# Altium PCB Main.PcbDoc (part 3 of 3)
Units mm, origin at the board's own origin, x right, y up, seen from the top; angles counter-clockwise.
Board outline 160.02 x 109 mm, 4 copper layers (Top Layer, MidLayer1, MidLayer2, Bottom Layer), stack 1.588 mm thick; 321 components, 271 nets, 1178 pads, 515 vias.
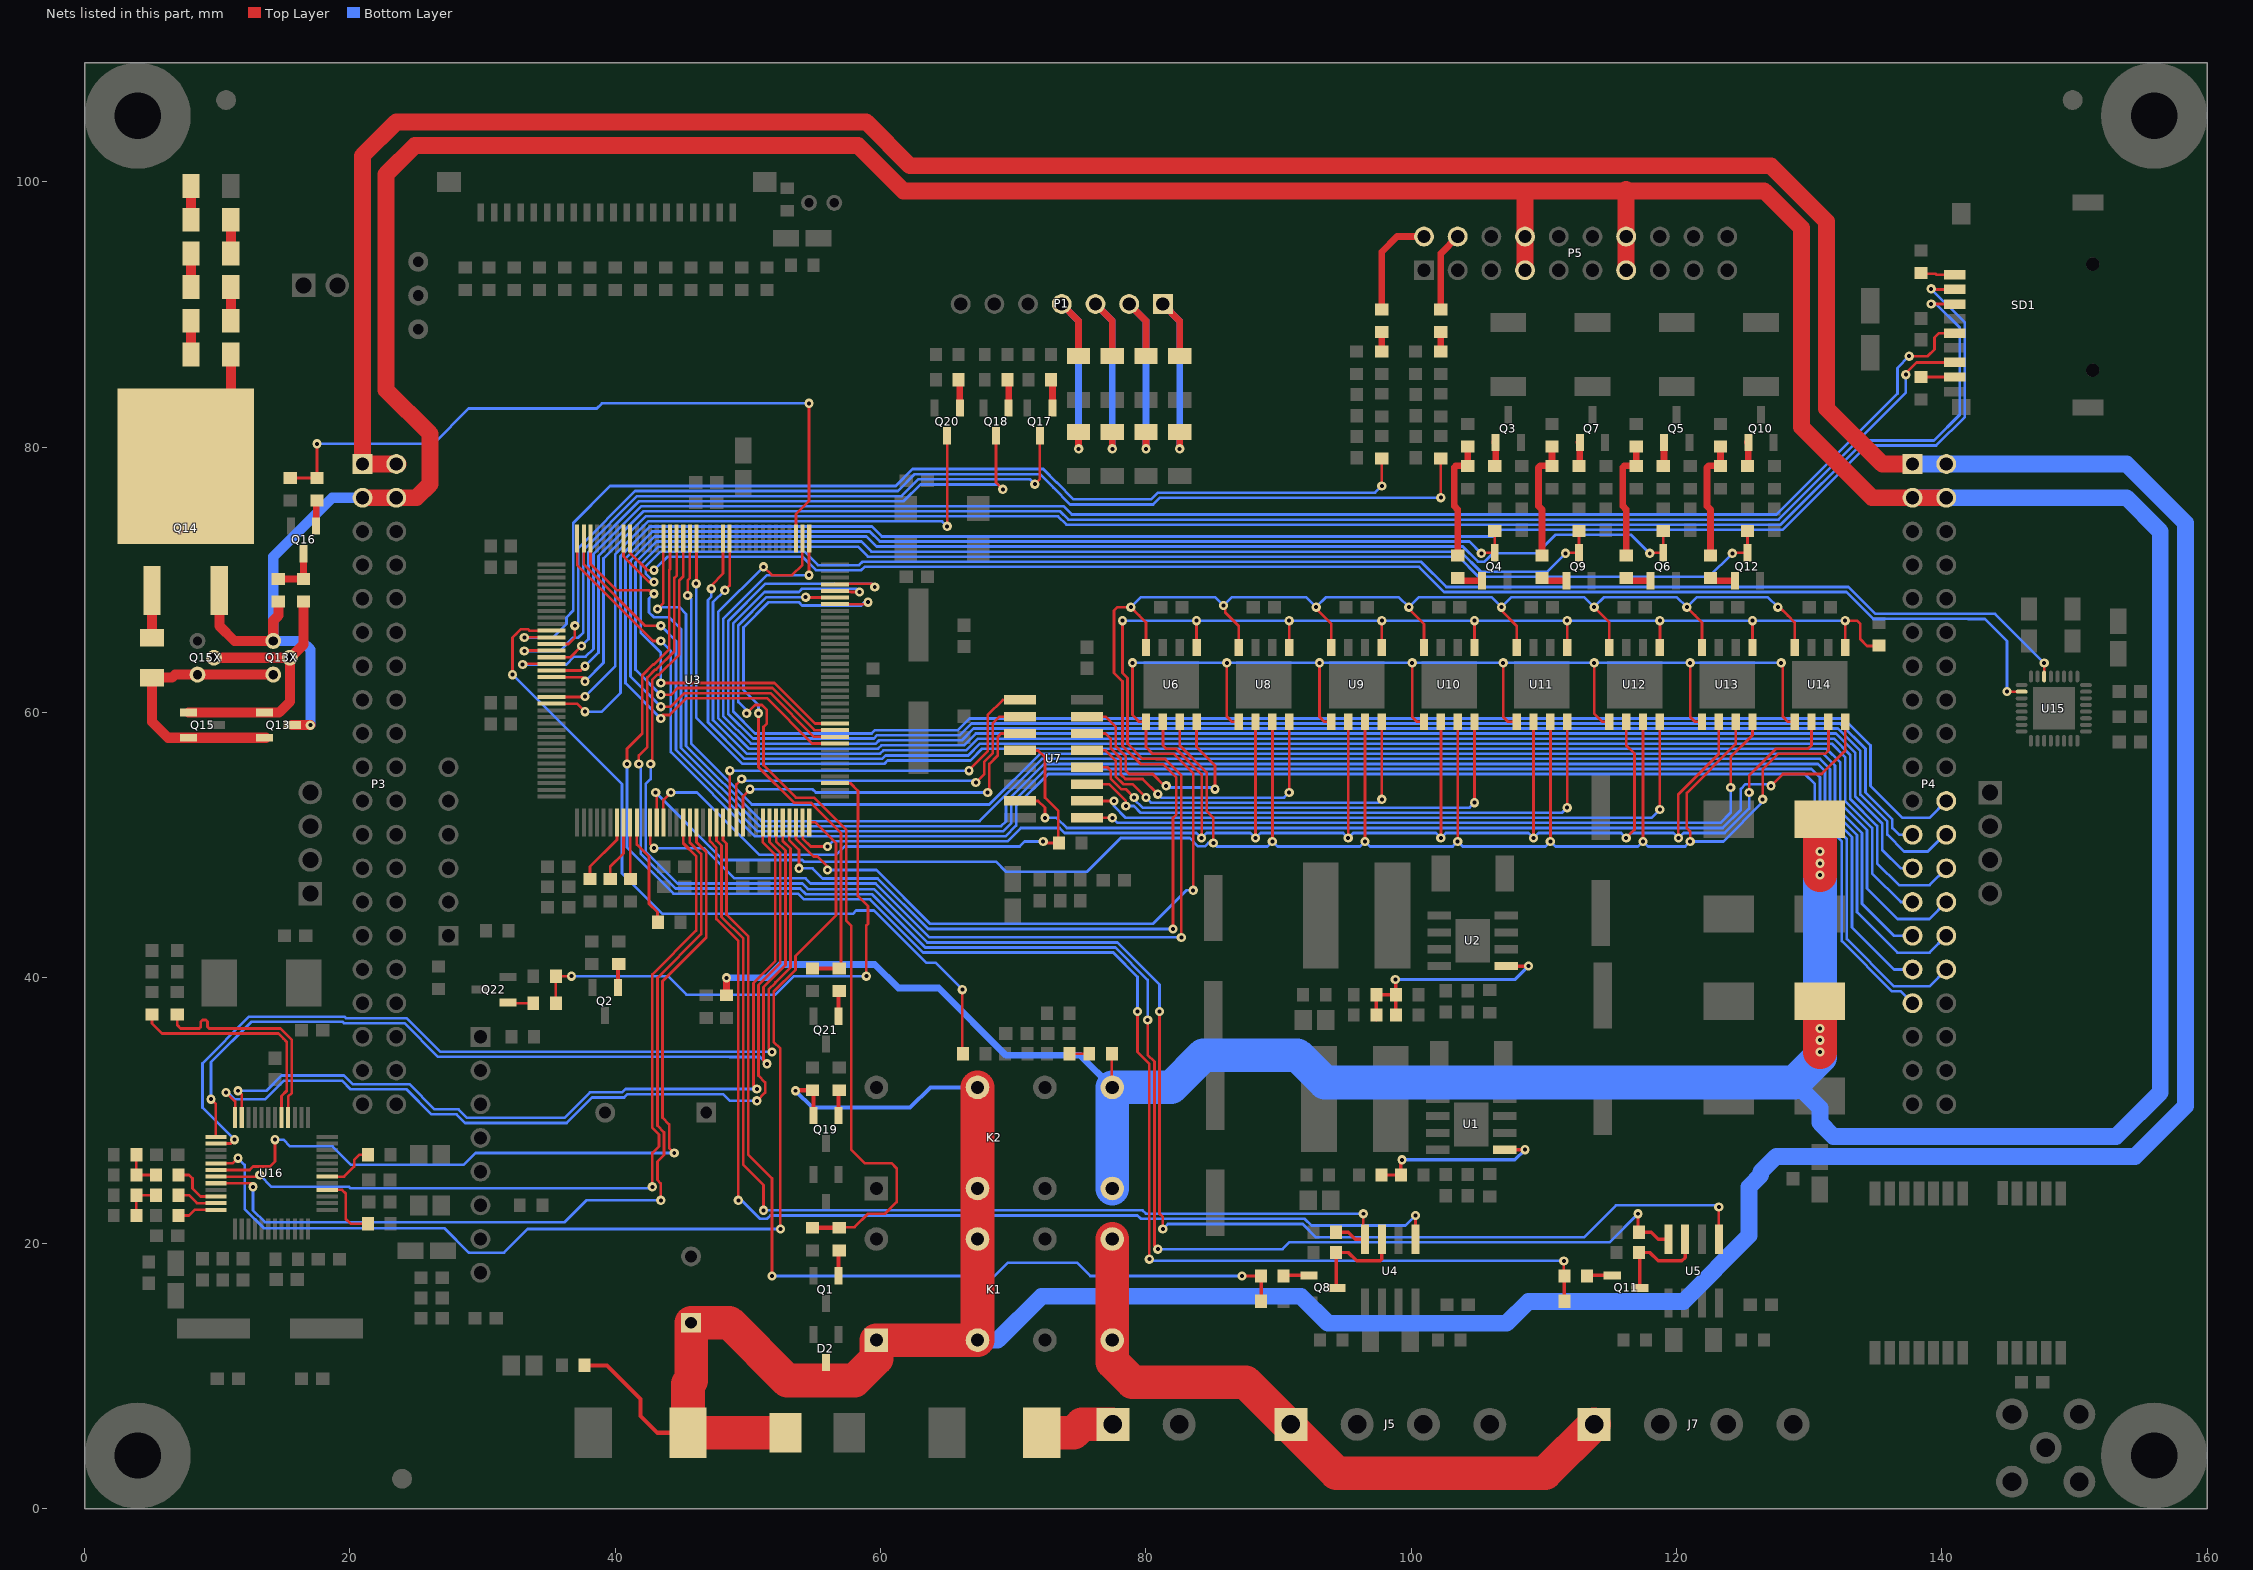
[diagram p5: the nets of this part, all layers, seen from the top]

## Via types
v1: diameter 0.7, hole 0.3, Top Layer to Bottom Layer, tented both sides, 515 vias

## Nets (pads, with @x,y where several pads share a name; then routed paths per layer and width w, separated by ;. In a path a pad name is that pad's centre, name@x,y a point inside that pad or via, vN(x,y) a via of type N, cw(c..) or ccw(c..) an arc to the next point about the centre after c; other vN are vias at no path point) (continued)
NetP4_22: P4.22 U3.104 | length 117.3
  Top Layer w0.203: U3.104@56.579,69.174 56.647,69.106 57.749,69.106 57.767,69.088 v1(58.42,69.088)
  Bottom Layer w0.203: v1(58.42,69.088) 58.172,69.336 54.095,69.336 53.847,69.088 51.245,69.088 48.901,66.743 48.901,60.064 50.539,58.426 59.334,58.426 59.588,58.68 65.824,58.68 66.707,59.563 132.588,59.563 134.62,57.531 134.62,54.483 137.033,52.07 139.065,52.07 P4.22@140.335,53.34
NetP4_23: P4.23 U3.105 | length 118.7
  Top Layer w0.203: U3.105@56.579,69.674 56.622,69.717 59.315,69.717 v1(59.563,69.469)
  Bottom Layer w0.203: v1(59.563,69.469) 59.309,69.723 51.341,69.723 48.52,66.901 48.52,59.906 50.381,58.045 59.492,58.045 59.746,58.299 65.981,58.299 66.865,59.182 132.334,59.182 134.239,57.277 134.239,53.975 136.271,51.943 136.271,51.308 136.779,50.8 P4.23@137.795,50.8
NetP4_24: P4.24 U3.109 | length 118.5
  Top Layer w0.203: v1(54.61,70.358) U3.109@54.61,73.279
  Bottom Layer w0.203: v1(54.61,70.358) 51.438,70.358 48.139,67.059 48.139,59.749 50.224,57.664 59.65,57.664 59.904,57.918 66.139,57.918 67.023,58.801 132.176,58.801 133.858,57.119 133.858,53.817 135.89,51.785 135.89,50.8 137.16,49.53 138.938,49.53 P4.24@140.335,50.927
NetP4_25: P4.25 U3.110 | length 117
  Top Layer w0.203: v1(51.181,70.993) 51.816,70.358 53.34,70.358 54.102,71.12 U3.110@54.102,73.025
  Bottom Layer w0.203: v1(51.181,70.993) 47.758,67.57 47.758,59.591 50.066,57.283 59.808,57.283 60.062,57.537 66.297,57.537 67.18,58.42 132.018,58.42 133.477,56.961 133.477,53.659 135.509,51.627 135.509,49.657 136.906,48.26 P4.25@137.795,48.26
NetP4_26: P4.26 U3.121 | length 117.4
  Top Layer w0.203: v1(48.26,69.215) 48.628,69.583 U3.121@48.628,73.126
  Bottom Layer w0.203: v1(48.26,69.215) 47.377,68.332 47.377,59.433 49.908,56.902 59.965,56.902 60.219,57.156 66.455,57.156 67.338,58.039 131.861,58.039 133.096,56.804 133.096,53.502 135.128,51.47 135.128,48.641 136.779,46.99 139.065,46.99 P4.26@140.335,48.26
NetP4_27: P4.27 U3.122 | length 115.6
  Top Layer w0.203: v1(47.244,69.342) 47.244,69.596 48.128,70.48 U3.122@48.128,73.126
  Bottom Layer w0.203: v1(47.244,69.342) 47.244,68.738 46.996,68.489 46.996,59.275 49.75,56.521 60.123,56.521 60.377,56.775 66.613,56.775 67.496,57.658 131.703,57.658 132.715,56.646 132.715,53.344 134.747,51.312 134.747,47.879 136.906,45.72 P4.27@137.795,45.72
NetP4_28: P4.28 U3.126 | length 119.9
  Top Layer w0.203: v1(46.101,69.723) 46.129,69.751 U3.126@46.129,73.126
  Bottom Layer w0.203: v1(46.101,69.723) 46.101,59.631 49.592,56.14 60.281,56.14 60.535,56.394 66.77,56.394 67.654,57.277 131.318,57.277 132.334,56.261 132.334,53.186 134.366,51.154 134.366,46.736 136.652,44.45 139.065,44.45 P4.28@140.335,45.72
NetP4_29: P4.29 U3.127 | length 121.8
  Top Layer w0.203: v1(45.466,68.834) 45.472,68.84 45.472,69.984 45.629,70.141 U3.127@45.629,73.126
  Bottom Layer w0.203: v1(45.466,68.834) 45.72,68.58 45.72,57.657 50.296,53.08 68.195,53.08 72.01,56.896 131.064,56.896 131.953,56.007 131.953,52.959 133.985,50.927 133.985,45.593 136.398,43.18 P4.29@137.795,43.18
NetP4_30: P4.30 U3.131 | length 128.9
  Top Layer w0.203: v1(43.18,67.818) 43.63,68.268 U3.131@43.63,73.126
  Bottom Layer w0.203: v1(43.18,67.818) 43.307,67.945 44.831,67.945 45.339,67.437 45.339,57.499 51.016,51.822 67.475,51.822 72.168,56.515 130.81,56.515 131.572,55.753 131.572,52.801 133.604,50.769 133.604,44.958 136.652,41.91 139.065,41.91 P4.30@140.335,43.18
NetP4_31: P4.31 U3.142 | length 131.3
  Top Layer w0.203: U3.142@38.131,73.126 38.131,71.216 40.132,69.215 42.545,69.215 42.799,68.961 v1(42.926,68.961)
  Bottom Layer w0.203: v1(42.926,68.961) 42.551,68.586 42.551,67.557 42.919,67.189 44.063,67.189 44.958,66.294 44.958,57.341 50.859,51.441 69.095,51.441 69.463,51.809 69.463,53.272 72.326,56.134 130.652,56.134 131.191,55.595 131.191,52.643 133.223,50.611 133.223,43.815 136.398,40.64 P4.31@137.795,40.64
NetP4_32: P4.32 U3.143 | length 133.9
  Top Layer w0.203: U3.143@37.631,73.126 37.631,71.177 42.26,66.548 v1(43.434,66.548)
  Bottom Layer w0.203: v1(43.434,66.548) 44.577,65.405 44.577,57.183 50.701,51.06 69.253,51.06 69.844,51.651 69.844,53.114 72.484,55.753 130.175,55.753 130.81,55.118 130.81,52.486 132.842,50.454 132.842,42.926 136.398,39.37 139.065,39.37 P4.32@140.335,40.64
NetP4_33: P4.33 U3.144 | length 131.3
  Top Layer w0.203: U3.144@37.131,73.126 37.131,71.138 42.864,65.405 v1(43.434,65.405)
  Bottom Layer w0.203: v1(43.434,65.405) 44.196,64.643 44.196,57.026 50.543,50.679 69.41,50.679 70.225,51.494 70.225,52.956 72.641,55.372 129.667,55.372 130.429,54.61 130.429,52.328 132.461,50.296 132.461,42.768 136.24,38.989 136.906,38.989 P4.33@137.795,38.1
NetP5_2: P5.2 R28.1 | length 8
  Top Layer w0.508: R28.1@97.79,90.385 97.79,94.742 98.933,95.885 P5.2@100.965,95.885
NetP5_4: P5.4 R36.1 | length 6
  Top Layer w0.508: R36.1@102.235,90.385 102.235,94.615 P5.4@103.505,95.885
NetQ1_1: Q1.1 R6.2 | length 1.8
  Top Layer w0.305: Q1.1@56.83,17.56 R6.2@56.83,19.365
NetQ2_1: Q2.1 R17.2 | length 1.7
  Top Layer w0.305: Q2.1@40.193,39.277 R17.2@40.193,40.955
NetQ3_1: Q3.1 R25.1 | length 1.6
  Top Layer w0.508: Q3.1@106.299,80.357 Q3.1@106.299,80.391 ; R25.1@106.365,78.801 Q3.1@106.365,80.357
NetQ4_1: Q4.1 R33.2 | length 1.9
  Top Layer w0.508: R33.2@103.505,70.104 103.666,69.943 Q4.1@105.349,69.943
NetQ4_3: Q4.3 R26.2 U3.81 | length 97.2
  Top Layer w0.203: v1(43.434,59.563) 43.434,59.69 43.567,59.823 44.105,59.823 45.37,61.087 51.435,61.087 54.845,57.677 U3.81@56.579,57.677 ; v1(105.283,72.009) 105.317,72.043 Q4.3@106.299,72.043 R26.2@106.299,73.699
  Bottom Layer w0.203: v1(43.434,59.563) 40.773,62.223 40.773,71.631 42.796,73.654 59.188,73.654 59.944,72.898 104.394,72.898 v1(105.283,72.009)
NetQ5_1: Q5.1 R41.1 | length 1.6
  Top Layer w0.508: Q5.1@118.999,80.357 Q5.1@118.999,80.391 ; R41.1@119.065,78.801 Q5.1@119.065,80.357
NetQ6_1: Q6.1 R45.2 | length 1.9
  Top Layer w0.508: R45.2@116.205,70.104 116.366,69.943 Q6.1@118.049,69.943
NetQ6_3: Q6.3 R42.2 U3.82 | length 109.4
  Top Layer w0.203: v1(43.434,60.452) 44.196,60.452 45.212,61.468 51.689,61.468 54.98,58.177 U3.82@56.579,58.177 ; v1(117.983,72.009) 118.017,72.043 Q6.3@118.999,72.043 R42.2@118.999,73.699
  Bottom Layer w0.203: v1(43.434,60.452) 41.154,62.731 41.154,71.473 42.954,73.273 58.934,73.273 59.69,72.517 103.885,72.517 105.022,71.38 105.544,71.38 106.179,72.015 109.48,72.015 110.871,73.406 116.586,73.406 v1(117.983,72.009)
NetQ7_1: Q7.1 R51.1 | length 1.6
  Top Layer w0.508: Q7.1@112.649,80.357 Q7.1@112.649,80.391 ; R51.1@112.715,78.801 Q7.1@112.715,80.357
NetQ8_1: Q8.1 R53.2 | length 1.7
  Top Layer w0.254: R53.2@90.612,17.587 Q8.1@92.295,17.587
NetQ8_3: Q8.3 R48.2 U4.3 | length 8
  Top Layer w0.254: Q8.3@94.361,16.51 94.361,19.304 95.25,19.304 95.885,18.669 97.663,18.669 97.79,18.796 U4.3@97.79,20.307
NetQ9_1: Q9.1 R58.2 | length 1.9
  Top Layer w0.508: R58.2@109.855,70.104 110.016,69.943 Q9.1@111.699,69.943
NetQ9_3: Q9.3 R52.2 U3.83 | length 100.4
  Top Layer w0.203: v1(43.434,61.341) 44.196,61.341 44.704,61.849 51.847,61.849 55.019,58.677 U3.83@56.579,58.677 ; v1(111.633,72.009) 111.667,72.043 Q9.3@112.649,72.043 R52.2@112.649,73.699
  Bottom Layer w0.203: v1(43.434,61.341) 41.535,63.239 41.535,71.315 43.112,72.892 58.553,72.892 59.309,72.136 103.727,72.136 105.245,70.618 107.817,70.618 107.823,70.612 110.236,70.612 v1(111.633,72.009)
NetQ10_1: Q10.1 R63.1 | length 1.6
  Top Layer w0.508: Q10.1@125.349,80.357 Q10.1@125.349,80.391 ; R63.1@125.415,78.801 Q10.1@125.415,80.357
NetQ11_1: Q11.1 R67.2 | length 1.9
  Top Layer w0.254: R67.2@113.223,17.587 Q11.1@115.155,17.587
NetQ11_3: Q11.3 R61.2 U5.3 | length 7.7
  Top Layer w0.254: Q11.3@117.221,16.764 117.221,19.304 117.983,19.304 118.618,18.669 120.396,18.669 120.65,18.923 U5.3@120.65,20.307
NetQ12_1: Q12.1 R70.2 | length 1.9
  Top Layer w0.508: R70.2@122.555,70.104 122.716,69.943 Q12.1@124.399,69.943
NetQ12_3: Q12.3 R64.2 U3.84 | length 111.5
  Top Layer w0.203: v1(43.434,62.23) 52.005,62.23 55.058,59.177 U3.84@56.579,59.177 ; v1(124.206,72.009) 124.147,72.009 124.113,72.043 Q12.3@125.349,72.043 R64.2@125.349,73.699
  Bottom Layer w0.203: v1(43.434,62.23) 43.434,64.515 41.916,66.033 41.916,71.158 43.269,72.511 58.299,72.511 59.055,71.755 103.569,71.755 105.093,70.231 122.428,70.231 v1(124.206,72.009)
NetQ13_1: Q13.1 Q13X.2 Q15.1 Q15X.2 R91.2 | length 21.7
  Top Layer w0.762: Q15.1@7.84,60.005 Q13.1@13.523,60.005 ; Q15X.2@9.755,64.135 Q13X.2@15.47,64.135 Q13X.2@15.494,64.135 ; Q13.1@13.555,60.005 14.666,60.005 15.494,60.833 Q13X.2@15.494,64.135 ; R91.2@16.51,68.365 16.51,65.151 Q13X.2@15.494,64.135
NetQ13_2: Q13.2 Q13X.3 Q15.2 Q15X.3 R89.1 | length 21.7
  Top Layer w0.762: R89.1@5.08,62.738 R89.1@5.08,62.635 ; Q13.2@13.655,58.105 Q13.2@13.555,58.105 Q15.2@7.84,58.105 6.284,58.105 5.08,59.309 R89.1@5.08,62.635 ; Q13X.3@14.224,62.865 Q15X.3@8.509,62.865 6.81,62.865 6.58,62.635 R89.1@5.08,62.635
NetQ14_1: Q14.1 R89.2 | length 3.7
  Top Layer w0.762: R89.2@5.08,65.532 R89.2@5.08,65.635 Q14.1@5.08,69.215
NetQ14_2: Q14.2 R124.1 | length 5.4
  Top Layer w0.762: Q14.2@11.025,81.637 R124.1@11.025,86.995
NetQ16_1: Q16.1 R93.2 | length 1.8
  Top Layer w0.508: Q16.1@17.46,74.075 R93.2@17.46,75.88
NetQ16_3: Q16.3 R90.2 R91.1 | length 3.7
  Top Layer w0.508: R90.2@14.605,70.065 R91.1@16.471,70.065 ; R91.1@16.51,70.104 Q16.3@16.51,71.975
NetQ17_1: Q17.1 R95.2 | length 2.1
  Top Layer w0.508: Q17.1@72.959,82.965 R95.2@72.959,85.029
NetQ17_3: Q17.3 U3.14 | length 53.5
  Top Layer w0.203: v1(33.147,64.643) 33.179,64.675 U3.14@35.179,64.675 ; v1(71.628,77.216) 72.009,77.597 Q17.3@72.009,80.865
  Bottom Layer w0.203: v1(33.147,64.643) 35.825,64.643 36.836,65.653 37.211,65.653 37.598,66.04 37.598,72.265 41.654,76.321 61.589,76.321 62.865,77.597 71.247,77.597 v1(71.628,77.216)
NetQ18_1: Q18.1 R97.2 | length 1.9
  Top Layer w0.508: Q18.1@69.657,82.965 R97.2@69.657,84.897
NetQ18_3: Q18.3 U3.15 | length 47.7
  Top Layer w0.203: U3.15@35.179,64.175 36.616,64.175 v1(37.465,65.024) ; Q18.3@68.707,80.865 68.707,77.343 v1(69.215,76.835)
  Bottom Layer w0.203: v1(37.465,65.024) 37.979,65.538 37.979,72.107 41.812,75.94 61.747,75.94 63.007,77.201 68.849,77.201 v1(69.215,76.835)
NetQ19_1: Q19.1 R98.1 | length 1.8
  Top Layer w0.305: Q19.1@56.83,29.625 R98.1@56.83,31.43
NetQ20_1: Q20.1 R99.2 | length 2.1
  Top Layer w0.508: Q20.1@65.974,82.965 R99.2@65.974,85.024
NetQ20_3: Q20.3 U3.21 | length 47.3
  Top Layer w0.203: U3.21@35.179,61.176 37.681,61.176 v1(37.719,61.214) ; v1(65.024,74.041) Q20.3@65.024,80.865
  Bottom Layer w0.203: v1(37.719,61.214) 40.011,63.506 40.011,71.947 42.48,74.416 64.649,74.416 v1(65.024,74.041)
NetQ21_1: Q21.1 R103.2 | length 1.9
  Top Layer w0.305: Q21.1@56.83,37.118 R103.2@56.83,39.05
NetQ22_1: Q22.1 R106.2 | length 1.9
  Top Layer w0.203: Q22.1@31.877,38.1 R106.2@33.821,38.1
NetR3_2: R3.2 R5.1 U1.5 | length 13.7
  Top Layer w0.254: R3.2@97.79,25.146 R5.1@99.226,25.146 99.226,26.201 v1(99.314,26.289) ; U1.5@107.061,27.051 v1(108.585,27.051)
  Bottom Layer w0.254: v1(99.314,26.289) 107.823,26.289 v1(108.585,27.051)
NetR6_1: R6.1 R7.1 U3.103 | length 67.5
  Top Layer w0.203: v1(49.911,59.944) 50.539,60.573 51.061,60.573 51.429,60.205 51.429,59.176 51.181,58.928 51.181,56.038 53.625,53.594 54.99,53.594 57.404,51.18 57.404,44.323 57.785,43.942 57.785,27.051 58.801,26.035 60.833,26.035 61.214,25.654 61.214,23.114 60.325,22.225 59.055,22.225 58.039,21.209 R6.1@56.896,21.209 ; v1(54.356,68.707) 54.389,68.674 U3.103@56.579,68.674
  Top Layer w0.305: R7.1@55.03,21.17 R6.1@56.896,21.17
  Bottom Layer w0.203: v1(49.911,59.944) 50.038,59.944 50.038,60.046 49.282,60.802 49.282,66.586 51.403,68.707 v1(54.356,68.707)
NetR9_2: R9.2 R10.2 R12.1 R13.1 U2.5 | length 18.3
  Top Layer w0.254: R10.2@97.37,36.83 R10.2@97.37,37.211 R9.2@97.37,38.696 ; R9.2@97.37,38.735 R12.1@98.845,38.735 ; v1(98.806,39.878) 98.845,39.839 R12.1@98.845,38.735 ; R13.1@98.845,36.869 R13.1@98.845,37.211 R12.1@98.845,38.735 ; U2.5@107.315,40.894 v1(108.839,40.894)
  Bottom Layer w0.254: v1(98.806,39.878) 107.823,39.878 v1(108.839,40.894)
NetR20_2: R20.2 R21.1 | length 1.4
  Top Layer w0.203: R21.1@74.295,34.29 R20.2@75.731,34.29
NetR23_2: R23.2 U3.11 | length 58.9
  Top Layer w0.203: v1(32.258,62.865) 32.258,65.659 32.518,65.919 ; 32.518,65.92 32.886,66.288 33.408,66.288 33.521,66.175 U3.11@35.179,66.175 ; R23.2@66.167,34.163 v1(66.167,39.116)
  Bottom Layer w0.203: v1(32.258,62.865) 40.513,54.61 40.513,47.878 43.56,44.831 57.911,44.831 58.159,45.079 59.51,45.079 63.441,41.148 64.135,41.148 v1(66.167,39.116)
NetR28_2: R28.2 R29.1 | length 1.6
  Top Layer w0.508: R29.1@97.79,87.21 R28.2@97.79,88.685 R28.2@97.79,88.773
NetR31_2: R31.2 U3.12 | length 79.5
  Top Layer w0.203: v1(33.147,65.659) 33.163,65.675 U3.12@35.179,65.675 ; v1(97.79,77.089) R31.2@97.79,79.121
  Bottom Layer w0.203: v1(33.147,65.659) 35.306,65.659 36.328,66.681 36.328,67.177 36.836,67.685 36.836,74.302 39.617,77.083 61.147,77.083 62.422,78.359 72.263,78.359 73.279,77.343 ; 73.279,77.337 73.285,77.337 74.549,76.073 80.391,76.073 80.899,76.581 97.282,76.581 v1(97.79,77.089)
NetR32_2: R32.2 R33.1 R35.1 | length 9.3
  Top Layer w0.508: R33.1@103.505,71.843 103.505,75.311 103.251,75.565 103.251,78.486 103.378,78.613 104.267,78.613 R32.2@104.267,80.049
NetR36_2: R36.2 R37.1 | length 1.6
  Top Layer w0.508: R37.1@102.235,87.21 R36.2@102.235,88.685 R36.2@102.235,88.773
NetR39_2: R39.2 U3.13 | length 80.1
  Top Layer w0.203: U3.13@35.179,65.175 36.473,65.175 36.957,65.659 v1(36.957,66.548) ; v1(102.235,76.2) R39.2@102.235,78.994
  Bottom Layer w0.203: v1(36.957,66.548) 37.217,66.808 37.217,72.423 41.496,76.702 61.305,76.702 62.58,77.978 72.009,77.978 73.025,76.962 ; 73.025,76.956 73.031,76.956 74.295,75.692 80.549,75.692 81.057,76.2 v1(102.235,76.2)
NetR44_2: R44.2 R45.1 R46.1 | length 9.3
  Top Layer w0.508: R45.1@116.205,71.843 116.205,75.311 115.951,75.565 115.951,78.486 116.078,78.613 116.967,78.613 R44.2@116.967,80.049
NetR47_2: R47.2 U3.58 U4.4 | length 80.1
  Top Layer w0.203: U3.58@47.629,51.726 47.629,50.346 48.006,49.969 48.006,44.608 49.657,42.957 49.657,25.908 51.181,24.384 v1(51.181,22.479) ; U4.4@96.393,20.574 v1(96.393,22.225)
  Top Layer w0.254: R47.2@94.361,20.828 95.25,20.828 95.771,20.307 U4.4@96.52,20.307
  Bottom Layer w0.203: v1(51.181,22.479) 79.756,22.479 80.004,22.231 96.399,22.231 v1(96.393,22.225)
NetR53_1: R53.1 R56.1 U3.59 | length 74.9
  Top Layer w0.203: U3.59@48.128,51.726 48.128,50.385 48.387,50.127 48.387,44.766 50.038,43.115 ; 50.038,43.053 50.038,26.67 51.816,24.892 v1(51.816,17.526) ; v1(87.249,17.526) R53.1@88.519,17.526
  Top Layer w0.254: R56.1@88.685,15.621 R53.1@88.685,17.311
  Bottom Layer w0.203: v1(51.816,17.526) 68.58,17.526 69.596,18.542 74.803,18.542 75.819,17.526 v1(87.249,17.526)
NetR57_2: R57.2 R58.1 R59.1 | length 9.3
  Top Layer w0.508: R58.1@109.855,71.843 109.855,75.311 109.601,75.565 109.601,78.486 109.728,78.613 110.617,78.613 R57.2@110.617,80.049
NetR60_2: R60.2 U3.129 U5.4 | length 129.1
  Top Layer w0.203: v1(41.783,56.134) 41.783,56.769 42.418,57.404 42.418,62.643 43.015,63.24 43.078,63.24 44.45,64.612 44.45,70.135 44.629,70.314 U3.129@44.629,73.126 ; v1(80.137,36.83) 80.137,34.194 80.645,33.686 80.645,19.812 v1(80.899,19.558) ; R60.2@117.094,20.701 117.094,20.828 v1(117.094,22.225)
  Top Layer w0.254: R60.2@117.094,20.828 R60.2@117.182,20.828 118.11,20.828 118.631,20.307 U5.4@119.38,20.307
  Bottom Layer w0.203: v1(41.783,56.134) 41.916,56.001 41.916,49.365 44.545,46.736 53.944,46.736 54.372,46.308 59.358,46.308 63.37,42.297 77.699,42.297 80.137,39.858 v1(80.137,36.83) ; v1(80.899,19.558) 90.297,19.558 90.805,20.066 114.935,20.066 v1(117.094,22.225)
NetR67_1: R67.1 R71.1 U3.130 | length 123
  Top Layer w0.203: v1(40.894,56.134) 40.894,57.277 42.037,58.42 42.037,62.801 42.858,63.621 42.92,63.621 44.069,64.77 44.069,70.739 44.129,70.799 U3.130@44.129,73.126 ; v1(79.375,37.465) 79.375,34.417 80.264,33.528 v1(80.264,18.796) ; R67.1@111.506,17.653 v1(111.506,18.669)
  Top Layer w0.254: R71.1@111.545,15.621 R67.1@111.545,17.438
  Bottom Layer w0.203: v1(40.894,56.134) 40.894,49.848 44.387,46.355 53.786,46.355 54.214,45.927 59.201,45.927 63.212,41.916 77.541,41.916 79.375,40.082 v1(79.375,37.465) ; v1(80.264,18.796) 80.385,18.675 111.5,18.675 v1(111.506,18.669)
NetR69_2: R69.2 R70.1 R72.1 | length 9.3
  Top Layer w0.508: R70.1@122.555,71.843 122.555,75.311 122.301,75.565 122.301,78.486 122.428,78.613 123.317,78.613 R69.2@123.317,80.049
NetR73_1: R73.1 U3.48 U6.5 U8.5 U9.5 U10.5 U11.5 U12.5 U13.5 U14.5 | length 144.7
  Top Layer w0.203: U3.48@42.63,51.726 42.63,50.08 v1(42.926,49.784) ; v1(78.232,66.929) 78.232,62.992 78.613,62.611 78.613,57.658 79.756,56.515 80.772,56.515 80.787,56.5 81.453,56.5 82.677,55.276 v1(82.677,43.053) ; v1(83.82,66.929) 83.82,65.206 U6.5@83.825,65.201 ; U8.5@90.805,64.897 v1(90.805,66.929) ; U9.5@97.79,65.024 v1(97.79,66.929) ; U10.5@104.775,64.897 v1(104.775,66.929) ; v1(111.76,66.929) 111.76,65.206 U11.5@111.765,65.201 ; v1(118.745,66.929) 118.75,66.924 U12.5@118.75,65.201 ; U13.5@125.735,65.201 v1@125.735,66.924 ; U14.5@132.715,64.897 v1(132.715,66.929) 133.604,66.929 133.858,66.675 133.858,65.532 134.366,65.024 R73.1@135.255,65.024
  Bottom Layer w0.203: v1(42.926,49.784) 46.705,49.784 48.986,47.504 54.349,47.504 54.736,47.117 59.627,47.117 63.686,43.059 82.671,43.059 v1(82.677,43.053) ; v1(78.232,66.929) v1(83.82,66.929) v1(90.805,66.929) v1(97.79,66.929) v1(104.775,66.929) v1(111.76,66.929) v1(118.745,66.929) v1(125.73,66.929) v1(132.715,66.929)
NetR74_2: R74.2 U3.50 U7.4 | length 42.8
  Top Layer w0.203: U3.50@43.63,51.726 43.63,53.409 v1(44.196,53.975) ; U7.4@70.739,57.15 71.882,57.15 72.39,56.642 72.39,53.594 73.406,52.578 R74.2@73.406,50.292 ; v1(72.263,50.292) 72.263,50.165 R74.2@73.406,50.165
  Bottom Layer w0.203: v1(44.196,53.975) 46.169,53.975 50.868,49.276 56.642,49.276 57.277,49.911 70.485,49.911 70.866,50.292 v1(72.263,50.292)
NetR93_1: R93.1 R94.1 U3.111 | length 53.5
  Top Layer w0.203: R94.1@15.582,77.685 R93.1@17.526,77.685 v1(17.526,80.264) ; U3.111@53.627,73.126 53.627,74.97 54.61,75.953 v1(54.61,83.312)
  Bottom Layer w0.203: v1(17.526,80.264) 26.289,80.264 28.956,82.931 38.608,82.931 38.989,83.312 v1(54.61,83.312)
NetR103_1: R103.1 R104.1 U3.102 | length 44.4
  Top Layer w0.203: v1(50.8,59.944) 50.8,55.88 53.467,53.213 54.741,53.213 55.059,52.896 55.059,52.891 57.023,50.927 57.023,40.855 R103.1@56.896,40.728 R103.1@56.896,40.64 ; U3.102@56.579,68.174 58.903,68.174 v1(59.055,68.326)
  Top Layer w0.305: R104.1@54.864,40.728 R103.1@56.73,40.728
  Bottom Layer w0.203: v1(50.8,59.944) 50.8,60.579 49.663,61.716 49.663,66.428 51.555,68.32 53.852,68.32 54.095,68.078 58.553,68.078 58.801,68.326 v1(59.055,68.326)
NetR106_1: R106.1 R107.1 U3.75 | length 42.7
  Top Layer w0.203: R106.1@35.521,38.1 R107.1@35.521,39.966 ; R107.1@35.521,40.132 v1(36.703,40.132) ; U3.75@56.579,54.678 57.72,54.678 58.294,54.104 58.294,51.554 ; 58.293,51.554 58.293,46.166 59.049,45.41 59.049,44.068 58.928,43.946 v1(58.928,40.132)
  Bottom Layer w0.203: v1(36.703,40.132) 43.978,40.132 45.375,38.735 52.07,38.735 53.467,40.132 v1(58.928,40.132)
NetR109_2: R109.2 R112.2 R116.1 | length 2.9
  Top Layer w0.203: R116.1@3.898,25.146 R109.2@3.898,26.631 ; R116.1@3.937,25.146 R112.2@5.373,25.146
NetR110_2: R110.2 R114.2 R117.1 | length 2.9
  Top Layer w0.203: R117.1@3.898,22.137 R110.2@3.898,23.622 ; R110.2@3.937,23.622 R114.2@5.373,23.622
NetR111_2: R111.2 U16.29 | length 17.2
  Top Layer w0.203: R111.2@5.08,37.211 5.08,36.576 5.842,35.814 8.509,35.814 8.515,35.808 14.612,35.808 14.98,35.44 ; U16.29@14.846,29.473 14.846,31.102 15.24,31.496 15.24,35.179 14.98,35.439
NetR112_1: R112.1 U16.46 | length 3.9
  Top Layer w0.203: R112.1@7.112,25.146 7.874,25.146 8.128,24.892 8.128,24.13 8.735,23.523 U16.46@9.896,23.523
NetR113_2: R113.2 U16.28 | length 17.1
  Top Layer w0.203: R113.2@6.985,37.465 R113.2@6.985,37.25 6.985,36.449 7.239,36.195 8.636,36.195 8.763,36.322 8.763,36.703 8.89,36.83 9.144,36.83 9.271,36.703 9.271,36.322 9.398,36.195 14.764,36.195 15.621,35.338 15.621,31.338 15.346,31.063 U16.28@15.346,29.473
NetR114_1: R114.1 U16.47 | length 3
  Top Layer w0.203: R114.1@7.112,23.622 7.874,23.622 8.473,23.023 U16.47@9.896,23.023
NetR115_1: R115.1 U16.48 | length 3
  Top Layer w0.203: R115.1@7.112,22.098 7.874,22.098 8.3,22.524 U16.48@9.896,22.524
NetR119_1: R119.1 U16.18 | length 4
  Top Layer w0.203: U16.18@18.296,25.023 19.562,25.023 20.32,25.781 20.32,26.289 20.701,26.67 R119.1@21.336,26.67
NetR120_1: R120.1 U16.16 | length 5.2
  Top Layer w0.203: U16.16@18.296,24.023 19.411,24.023 19.685,23.749 19.685,21.844 20.066,21.463 R120.1@21.336,21.463
NetR121_2: R121.2 SD1.8 | length 2.5
  Top Layer w0.203: R121.2@138.43,85.305 SD1.8@140.931,85.305
NetR122_2: R122.2 SD1.1 | length 2.6
  Top Layer w0.203: R122.2@138.43,93.091 139.516,93.091 139.608,92.999 SD1.1@140.97,92.999
NetR124_2: R124.2 R125.1 | length 2.4
  Top Layer w0.762: R124.2@8.025,87.098 R125.1@8.025,89.535
NetR125_2: R125.2 R126.1 | length 2.4
  Top Layer w0.762: R125.2@11.025,89.638 R126.1@11.025,92.075
NetR126_2: R126.2 R127.1 | length 2.6
  Top Layer w0.762: R126.2@8.025,91.972 R126.2@8.025,92.075 R127.1@8.025,94.615
NetR127_2: R127.2 R128.1 | length 2.5
  Top Layer w0.762: R127.2@11.025,94.639 R128.1@11.025,97.155
NetR128_2: R128.2 R129.1 | length 2.5
  Top Layer w0.762: R128.2@8.025,97.179 R129.1@8.025,99.695
NetR130_2: R130.2 U3.43 | length 5.1
  Top Layer w0.203: R130.2@38.227,47.498 38.1,47.625 38.1,48.387 40.13,50.417 U3.43@40.13,51.726
NetR131_2: R131.2 U3.44 | length 4.6
  Top Layer w0.203: R131.2@39.624,47.498 39.624,48.387 40.63,49.393 U3.44@40.63,51.726
NetR132_2: R132.2 U3.45 | length 4.2
  Top Layer w0.203: U3.45@41.13,51.726 41.13,47.516 R132.2@41.148,47.498
NetR133_2: R133.2 U3.46 | length 8.2
  Top Layer w0.203: U3.46@41.63,51.726 41.63,50.064 42.545,49.149 42.545,45.593 43.18,44.958 R133.2@43.18,44.196
NetSD1_2: SD1.2 U3.22 | length 135.2
  Top Layer w0.203: U3.22@35.179,60.676 37.114,60.676 v1(37.719,60.071) ; v1@139.192,91.899 SD1.2@140.97,91.899
  Bottom Layer w0.203: v1(37.719,60.071) 38.989,60.071 40.392,61.474 40.392,71.789 42.638,74.035 59.345,74.035 60.102,73.279 106.299,73.279 106.807,73.787 128.016,73.787 134.366,80.137 139.573,80.137 141.732,82.296 141.732,89.408 v1(139.192,91.948)
NetSD1_3: SD1.3 U3.18 | length 131.1
  Top Layer w0.203: U3.18@35.179,62.676 37.527,62.676 37.719,62.484 v1(37.719,62.357) ; v1(139.192,90.805) 140.843,90.805 SD1.3@140.97,90.932
  Bottom Layer w0.203: v1(37.719,62.357) 39.122,63.76 39.122,71.6 39.136,71.614 ; 39.122,71.628 42.291,74.797 73.375,74.797 74.005,74.168 127.858,74.168 134.208,80.518 139.415,80.518 141.351,82.454 141.351,89.027 139.573,90.805 v1(139.192,90.805)
NetSD1_5: SD1.5 U3.16 | length 126.8
  Top Layer w0.203: v1(33.02,63.627) 33.068,63.675 U3.16@35.179,63.675 ; v1(137.541,86.868) 138.938,86.868 139.446,87.376 139.446,88.265 139.78,88.599 SD1.5@140.97,88.599
  Bottom Layer w0.203: v1(33.02,63.627) 36.322,63.627 36.909,64.214 37.767,64.214 38.36,64.806 38.36,71.949 41.97,75.559 73.793,75.559 74.422,74.93 86.233,74.93 ; 86.264,74.93 127.543,74.93 136.658,84.045 136.658,85.985 v1(137.541,86.868)
NetSD1_7: SD1.7 U3.17 | length 121
  Top Layer w0.203: U3.17@35.179,63.176 37.395,63.176 v1(37.719,63.5) ; v1(137.287,85.471) 137.414,85.598 137.414,85.725 138.088,86.399 SD1.7@140.97,86.399
  Bottom Layer w0.203: v1(37.719,63.5) 38.741,64.522 38.741,71.791 42.128,75.178 73.533,75.178 74.162,74.549 127.7,74.549 137.287,84.136 v1(137.287,85.471)
NetU3_49: U3.49 U6.3 U8.3 U9.3 U10.3 U11.3 U12.3 U13.3 U14.3 | length 166.4
  Top Layer w0.203: v1(43.053,53.975) 43.13,53.898 U3.49@43.13,51.726 ; U6.3@82.555,58.978 82.555,57.526 84.582,55.499 84.582,52.578 85.09,52.07 v1(85.09,50.165) ; v1(89.535,50.292) 89.54,50.297 U8.3@89.54,58.978 ; v1(96.52,50.292) 96.525,50.297 U9.3@96.525,58.978 ; v1(103.505,50.292) 103.51,50.297 U10.3@103.51,58.978 ; v1(110.49,50.292) 110.495,50.297 U11.3@110.495,58.978 ; v1(117.475,50.292) 117.48,50.297 U12.3@117.48,58.978 ; v1(121.031,50.292) 121.031,51.054 120.783,51.302 120.783,53.95 124.46,57.627 U13.3@124.46,59.309 ; v1(126.492,53.467) 126.492,55.721 127.651,56.88 ; 127.667,56.896 131.191,56.896 131.45,57.155 U14.3@131.45,58.978
  Bottom Layer w0.203: v1(43.053,53.975) 48.139,48.889 54.109,48.889 54.23,48.768 68.707,48.768 69.469,48.006 75.565,48.006 78.105,50.546 83.311,50.546 83.94,49.917 84.462,49.917 84.71,50.165 v1(85.09,50.165) 85.344,49.911 89.154,49.911 v1(89.535,50.292) 89.916,49.911 96.139,49.911 v1(96.52,50.292) 96.901,49.911 103.124,49.911 v1(103.505,50.292) 103.886,49.911 110.109,49.911 v1(110.49,50.292) 110.871,49.911 117.094,49.911 v1(117.475,50.292) 117.856,49.911 120.65,49.911 v1(121.031,50.292) 123.536,50.292 126.492,53.248 v1(126.492,53.467)
NetU3_53: U3.53 U16.43 | length 63.1
  Top Layer w0.203: U16.43@9.896,25.023 13.085,25.023 v1(13.208,25.146) ; v1(42.799,24.257) 42.799,26.808 43.301,27.311 43.301,28.201 42.799,28.703 42.799,40.259 46.101,43.561 46.101,49.18 45.129,50.152 U3.53@45.129,51.726
  Bottom Layer w0.203: v1(13.208,25.146) 14.097,24.257 19.938,24.257 20.059,24.136 42.678,24.136 v1(42.799,24.257)
NetU3_54: U3.54 U16.44 | length 67.2
  Top Layer w0.203: U16.44@9.896,24.523 12.561,24.523 v1@12.7,24.384 ; v1(43.434,23.241) 43.428,23.247 43.428,24.518 43.18,24.766 43.18,26.148 43.682,26.65 43.682,28.359 43.18,28.861 43.18,40.005 46.482,43.307 46.482,49.338 45.629,50.191 U3.54@45.629,51.726
  Bottom Layer w0.203: v1(12.7,24.257) 12.7,22.479 13.589,21.59 36.195,21.59 37.846,23.241 v1(43.434,23.241)
NetU3_55: U3.55 U16.42 | length 64.6
  Top Layer w0.203: U16.42@9.896,25.523 12.442,25.523 12.7,25.781 13.97,25.781 14.351,26.162 v1(14.351,27.813) ; v1(44.45,26.797) 44.063,27.184 44.063,28.962 43.561,29.464 43.561,39.751 46.863,43.053 46.863,49.495 46.129,50.23 U3.55@46.129,51.726
  Bottom Layer w0.203: v1(14.351,27.813) 14.986,27.813 15.494,27.305 18.7,27.305 20.097,25.908 28.575,25.908 29.464,26.797 v1(44.45,26.797)
NetU3_57: U3.57 U4.1 | length 83.5
  Top Layer w0.203: U3.57@47.129,51.726 47.129,50.307 47.625,49.811 47.625,44.45 49.276,42.799 v1(49.276,23.241) ; U4.1@100.33,20.32 v1(100.33,22.098)
  Bottom Layer w0.203: v1(49.276,23.241) 49.529,23.241 50.92,21.85 51.442,21.85 51.69,22.098 79.375,22.098 79.623,21.85 91.974,21.85 92.488,21.336 99.568,21.336 v1(100.33,22.098)
NetU3_60: U3.60 U7.1 | length 28.3
  Top Layer w0.203: U3.60@48.628,51.726 v1@48.628,55.626 ; v1(66.675,55.626) 66.675,55.689 68.072,57.086 68.072,59.817 69.215,60.96
  Bottom Layer w0.203: v1(48.641,55.626) v1(66.675,55.626)
NetU3_61: U3.61 U7.2 | length 28.4
  Top Layer w0.203: U3.61@49.128,51.726 49.128,54.589 v1(49.53,54.991) ; v1(67.183,54.737) 67.824,55.378 67.824,56.299 68.453,56.928 68.453,59.182 68.966,59.695 U7.2@70.5,59.695
  Bottom Layer w0.203: v1(49.53,54.991) 49.663,54.858 67.062,54.858 v1(67.183,54.737)
NetU3_62: U3.62 U7.3 | length 27
  Top Layer w0.203: U3.62@49.628,51.726 49.628,53.692 v1(50.165,54.229) ; v1(68.072,53.975) 68.205,54.108 68.205,56.141 68.834,56.77 68.834,58.166 69.088,58.42 U7.3@70.485,58.42
  Bottom Layer w0.203: v1(50.165,54.229) 50.171,54.223 54.871,54.223 55.119,53.975 v1(68.072,53.975)
NetU3_65: U3.65 U16.35 | length 65.2
  Top Layer w0.203: v1(11.557,31.496) 11.847,31.206 U16.35@11.847,29.473 ; v1(50.673,31.623) 50.419,31.877 50.419,39.624 52.07,41.275 52.07,49.276 51.128,50.218 U3.65@51.128,51.726
  Bottom Layer w0.203: v1(11.557,31.496) 13.716,31.496 14.859,32.639 19.558,32.639 20.206,31.991 24.493,31.991 26.385,30.099 28.194,30.099 28.842,29.451 36.182,29.451 38.106,31.375 40.52,31.375 40.768,31.623 v1(50.673,31.623)
NetU3_66: U3.66 U16.36 | length 67.9
  Top Layer w0.203: v1(10.668,31.369) 11.347,30.69 U16.36@11.347,29.473 ; v1@50.674,30.734 51.302,31.362 51.302,32.132 50.8,32.635 50.8,39.466 52.451,41.117 52.451,49.434 51.628,50.257 U3.66@51.628,51.726
  Bottom Layer w0.203: v1(10.668,31.369) 10.794,31.369 11.296,30.867 13.625,30.867 15.017,32.258 19.4,32.258 20.048,31.61 24.257,31.61 26.149,29.718 28.036,29.718 28.684,29.07 36.34,29.07 38.263,30.994 40.678,30.994 40.926,31.242 48.133,31.242 48.641,30.734 v1(50.673,30.734)
NetU3_67: U3.67 U16.37 | length 69.5
  Top Layer w0.203: v1(9.525,30.861) 9.896,30.49 U16.37@9.896,28.022 ; v1(51.435,33.528) 51.181,33.782 51.181,39.308 52.832,40.959 52.832,49.592 52.127,50.296 U3.67@52.127,51.726
  Bottom Layer w0.203: v1(9.525,30.861) 9.525,33.655 12.567,36.697 19.438,36.697 19.546,36.589 24.117,36.589 26.657,34.049 48.628,34.049 ; 48.641,34.036 50.927,34.036 v1(51.435,33.528)
NetU3_68: U3.68 U16.38 | length 72.1
  Top Layer w0.203: U16.38@9.896,27.522 11.012,27.522 v1(11.303,27.813) ; v1(51.816,34.417) 51.562,34.671 51.562,39.116 52.07,39.624 52.07,39.659 53.213,40.802 53.213,49.749 52.627,50.335 U3.68@52.627,51.726
  Bottom Layer w0.203: v1(11.303,27.813) 8.896,30.22 8.896,33.564 12.41,37.078 19.596,37.078 19.704,36.97 24.275,36.97 26.815,34.43 51.803,34.43 v1(51.816,34.417)
NetU3_69: U3.69 U6.8 U8.8 U9.8 U10.8 U11.8 U12.8 U13.8 U14.8 | length 140.2
  Top Layer w0.203: U3.69@53.127,51.726 53.127,50.377 53.848,49.656 v1(53.848,48.26) ; v1(78.867,67.945) 79.495,67.316 80.01,66.802 80.01,65.206 U6.8@80.015,65.201 ; v1(78.867,67.945) 77.851,67.945 77.597,67.691 77.597,62.992 78.232,62.357 78.232,57.5 79.614,56.119 81.295,56.119 82.296,55.118 82.296,52.324 82.042,52.07 v1(82.042,43.688) ; v1(85.852,68.072) 85.979,67.945 85.979,67.564 86.995,66.548 86.995,65.206 U8.8@87,65.201 ; v1@92.964,67.691 93.98,66.675 93.98,65.206 U9.8@93.985,65.201 ; v1@99.949,67.691 100.97,66.67 U10.8@100.97,65.201 ; v1(106.807,67.945) 106.807,67.691 107.95,66.548 107.95,65.206 U11.8@107.955,65.201 ; v1@113.919,67.817 114.42,67.316 114.94,66.797 U12.8@114.94,65.201 ; 121.031,67.69 121.405,67.316 121.925,66.797 U13.8@121.925,65.201 ; v1@127.636,67.944 127.761,67.944 128.39,67.316 128.91,66.797 U14.8@128.91,65.201
  Bottom Layer w0.203: v1(53.848,48.26) 54.864,48.26 55.626,47.498 59.785,47.498 63.595,43.688 v1(82.042,43.688) ; v1(78.867,67.945) 79.628,68.707 85.217,68.707 v1(85.852,68.072) 86.487,68.707 92.075,68.707 v1(92.837,67.945) ; v1(92.837,67.945) 93.598,68.707 99.06,68.707 v1(99.822,67.945) ; v1(99.822,67.945) 100.583,68.707 106.045,68.707 v1(106.807,67.945) ; v1(106.807,67.945) 107.568,68.707 113.03,68.707 v1(113.792,67.945) ; v1(113.792,67.945) 114.553,68.707 120.015,68.707 v1(120.777,67.945) ; v1(120.777,67.945) 121.538,68.707 126.873,68.707 v1(127.635,67.945)
NetU3_70: U3.70 U6.1 U8.1 U9.1 U10.1 U11.1 U12.1 U13.1 U14.1 | length 140.9
  Top Layer w0.203: U3.70@53.627,51.726 53.627,50.482 54.96,49.149 55.245,49.149 56.007,48.387 v1(56.007,48.133) ; v1(78.994,63.754) 78.994,59.817 79.502,59.309 U6.1@80.01,59.309 ; U6.1@80.015,59.309 80.015,57.399 80.518,56.896 82.107,56.896 83.566,55.437 v1(83.566,46.609) ; v1(86.106,63.754) 86.106,59.69 86.487,59.309 U8.1@86.995,59.309 ; v1(93.091,63.754) 93.091,59.69 93.472,59.309 U9.1@93.98,59.309 ; v1(100.076,63.754) 100.076,59.69 100.457,59.309 U10.1@100.965,59.309 ; U10.1@100.97,58.978 U10.1@100.97,59.309 ; v1(106.934,63.754) 106.934,59.69 107.315,59.309 U11.1@107.95,59.309 ; U11.1@107.955,58.978 U11.1@107.955,59.309 ; v1(113.792,63.754) 113.792,59.944 114.427,59.309 U12.1@114.935,59.309 ; v1(121.031,63.754) 121.031,59.69 121.412,59.309 U13.1@121.92,59.309 ; v1(127.889,63.754) 128.016,63.627 128.016,59.69 128.397,59.309 U14.1@128.905,59.309
  Bottom Layer w0.203: v1(56.007,48.133) 59.689,48.133 63.747,44.075 80.52,44.075 83.054,46.609 v1(83.566,46.609) ; v1(78.994,63.754) v1(86.106,63.754) v1(93.091,63.754) v1(100.076,63.754) v1(106.934,63.754) v1(113.792,63.754) v1(121.031,63.754) v1(127.889,63.754)
NetU3_71: U3.71 U6.2 U8.2 U9.2 U10.2 U11.2 U12.2 U13.2 U14.2 | length 148.4
  Top Layer w0.203: U3.71@54.127,51.726 54.127,50.521 54.737,49.911 v1(56.007,49.911) ; U6.2@81.285,58.978 81.285,57.526 81.534,57.277 82.265,57.277 84.201,55.341 v1(84.201,50.546) ; v1@88.265,50.673 88.27,50.678 U8.2@88.27,58.978 ; v1(95.25,50.546) 95.255,50.551 U9.2@95.255,58.978 ; v1(102.235,50.546) 102.24,50.551 U10.2@102.24,58.978 ; v1(109.22,50.546) 109.225,50.551 U11.2@109.225,58.978 ; v1(116.205,50.546) 116.84,51.181 116.84,56.906 116.21,57.536 U12.2@116.21,58.978 ; v1(120.142,50.546) 120.142,53.848 123.195,56.901 U13.2@123.195,58.978 ; v1(125.476,53.975) 125.476,55.245 126.238,56.007 ; 126.239,56.006 127.509,57.277 129.921,57.277 130.18,57.536 U14.2@130.18,58.978
  Bottom Layer w0.203: v1(56.007,49.911) 56.394,50.298 69.568,50.298 70.579,51.308 73.502,51.308 73.883,50.927 83.82,50.927 v1(84.201,50.546) 84.582,50.927 87.884,50.927 v1(88.265,50.546) 88.646,50.927 94.869,50.927 v1(95.25,50.546) 95.631,50.927 101.854,50.927 v1(102.235,50.546) 102.616,50.927 108.839,50.927 v1(109.22,50.546) 109.601,50.927 115.824,50.927 v1(116.205,50.546) 116.586,50.927 119.761,50.927 v1(120.142,50.546) 120.523,50.927 123.633,50.927 125.476,52.77 v1(125.476,53.975)
NetU3_72: U3.72 U16.41 | length 82.3
  Top Layer w0.203: U16.41@9.896,26.023 11.164,26.023 v1(11.557,26.416) ; v1(52.451,21.082) 52.451,30.607 52.445,30.613 52.445,34.678 51.943,35.18 51.943,38.958 53.594,40.609 53.594,41.656 56.642,44.704 56.642,50.166 55.082,51.726 U3.72@54.627,51.726
  Bottom Layer w0.203: v1(11.557,26.416) 12.071,25.902 12.071,22.57 13.51,21.13 27.13,21.13 28.956,19.304 ; 28.956,19.291 31.61,19.291 33.401,21.082 v1(52.451,21.082)
NetU3_128: U3.128 U5.1 | length 132
  Top Layer w0.203: v1(42.672,56.134) 42.799,56.261 42.799,62.485 43.173,62.859 43.301,62.859 44.831,64.389 44.831,69.977 45.129,70.275 U3.128@45.129,73.126 ; v1(81.026,37.465) 81.026,22.225 81.28,21.971 v1(81.28,21.082) ; U5.1@123.19,20.574 v1(123.19,22.733)
  Bottom Layer w0.203: v1(42.672,56.134) 42.672,54.991 42.297,54.616 42.297,49.523 44.703,47.117 54.102,47.117 54.53,46.689 59.516,46.689 63.528,42.678 77.857,42.678 81.026,39.508 v1(81.026,37.465) ; v1(81.28,21.082) 81.655,21.457 91.828,21.457 92.838,20.447 113.029,20.447 115.436,22.854 123.069,22.854 v1(123.19,22.733)
NetU3_136: U3.136 U15.2 | length 113.6
  Top Layer w0.203: U3.136@41.13,73.126 41.13,72.024 42.415,70.739 v1(42.926,70.739) ; v1(144.907,61.595) 144.927,61.575 U15.2@146.013,61.575
  Bottom Layer w0.203: v1(42.926,70.739) 43.936,71.749 54.109,71.749 55.119,70.739 58.547,70.739 58.801,70.993 100.584,70.993 102.489,69.088 132.81,69.088 134.836,67.062 135.674,67.062 135.681,67.069 141.986,67.069 ; 141.986,67.056 143.256,67.056 144.907,65.405 v1(144.907,61.595)
NetU3_137: U3.137 U15.30 | length 116.5
  Top Layer w0.203: U3.137@40.63,73.126 40.63,71.765 42.545,69.85 v1(42.926,69.85) ; U15.30@147.713,62.725 v1(147.713,63.742)
  Bottom Layer w0.203: v1(42.926,69.85) 42.297,70.478 42.297,71 43.427,72.13 54.267,72.13 55.277,71.12 58.389,71.12 58.643,71.374 100.742,71.374 102.647,69.469 132.969,69.469 134.626,67.812 134.994,67.443 135.516,67.443 135.523,67.45 144.005,67.45 v1(147.713,63.742)
NFLASH_CS0: U6.4 U7.15 | length 19.1
  Top Layer w0.203: U7.15@75.438,59.69 U7.15@75.58,59.69 ; U7.15@75.58,59.695 76.957,59.695 77.739,58.913 77.739,57.45 78.486,56.704 78.486,55.626 78.739,55.373 80.517,55.373 81.406,54.483 v1(81.534,54.483) ; U6.4@83.82,59.182 83.82,57.404 85.217,56.007 v1(85.217,54.229)
  Bottom Layer w0.203: v1(81.534,54.483) 81.661,54.356 85.09,54.356 v1(85.217,54.229)
NFLASH_CS1: U7.14 U8.4 | length 23.1
  Top Layer w0.203: U7.14@75.819,58.42 76.962,58.42 77.358,58.024 77.358,57.292 78.105,56.546 78.105,55.339 78.452,54.992 79.755,54.992 v1(80.899,53.848) ; v1(90.805,53.975) U8.4@90.805,58.801
  Bottom Layer w0.203: v1(80.899,53.848) 81.153,53.594 90.424,53.594 v1(90.805,53.975)
NFLASH_CS2: U7.13 U9.4 | length 30.5
  Top Layer w0.203: U7.13@75.58,57.155 76.962,57.155 ; 76.962,57.15 77.724,56.388 77.724,55.181 78.294,54.611 78.995,54.611 v1(80.01,53.594) ; v1(97.79,53.467) U9.4@97.79,59.309
  Bottom Layer w0.203: v1(80.01,53.594) 80.391,53.213 97.536,53.213 v1(97.79,53.467)
NFLASH_CS3: U7.12 U10.4 | length 37.1
  Top Layer w0.203: U7.12@75.58,55.885 U7.12@75.946,55.885 ; U7.12@75.946,55.88 77.089,55.88 77.343,55.626 77.343,55.023 78.136,54.23 78.485,54.23 v1(79.121,53.594) ; v1(104.775,53.213) U10.4@104.775,59.309
  Bottom Layer w0.203: v1(79.121,53.594) 79.121,53.467 79.756,52.832 104.394,52.832 v1(104.775,53.213)
NFLASH_CS4: U7.11 U11.4 | length 43.7
  Top Layer w0.203: U7.11@75.438,54.61 77.217,54.61 78.486,53.341 v1(78.486,52.959) ; v1(111.76,52.832) U11.4@111.76,58.928
  Bottom Layer w0.203: v1(78.486,52.959) 79.09,52.959 79.598,52.451 111.379,52.451 v1(111.76,52.832)
NFLASH_CS5: U7.10 U12.4 | length 50
  Top Layer w0.203: U7.10@75.819,53.34 v1(77.597,53.34) ; v1(118.745,52.705) U12.4@118.745,58.801
  Bottom Layer w0.203: v1(77.597,53.34) 77.597,52.958 78.485,52.07 118.11,52.07 v1(118.745,52.705)
NFLASH_CS6: U7.9 U13.4 | length 56.1
  Top Layer w0.203: U7.9@75.565,52.07 v1(77.47,52.07) ; v1(124.079,54.356) 124.079,56.642 125.73,58.293 U13.4@125.73,58.928
  Bottom Layer w0.203: v1(77.47,52.07) 77.851,51.689 123.317,51.689 124.079,52.451 v1(124.079,54.356)
NFLASH_CS7: U7.7 U14.4 | length 68.8
  Top Layer w0.203: U7.7@70.485,53.34 71.882,53.34 72.39,52.832 v1(72.39,52.07) ; v1(127.127,54.483) 128.016,55.372 130.937,55.372 132.72,57.155 U14.4@132.72,58.978
  Bottom Layer w0.203: v1(72.39,52.07) 73.279,52.07 74.041,51.308 123.475,51.308 124.847,52.68 124.847,54.236 125.215,54.604 127.006,54.604 v1(127.127,54.483)
R1: D15.1 D16.1 P1.1 | length 17.2
  Top Layer w0.508: P1.1@81.28,90.805 82.55,89.535 D15.1@82.55,86.867 ; v1(82.55,79.883) D16.1@82.55,81.152
  Bottom Layer w0.508: P1.1@81.28,90.805 82.55,89.535 v1(82.55,79.883)
R2: D17.1 D18.1 P1.2 | length 17.2
  Top Layer w0.508: P1.2@78.74,90.805 80.01,89.535 D17.1@80.01,86.867 ; v1(80.01,79.883) D18.1@80.01,81.152
  Bottom Layer w0.508: P1.2@78.74,90.805 80.01,89.535 v1(80.01,79.883)
R3: D20.1 D21.1 P1.3 | length 17.2
  Top Layer w0.508: P1.3@76.2,90.805 77.47,89.535 D20.1@77.47,86.867 ; v1(77.47,79.883) D21.1@77.47,81.152
  Bottom Layer w0.508: P1.3@76.2,90.805 77.47,89.535 v1(77.47,79.883)
R4: D22.1 D23.1 P1.4 | length 17.2
  Top Layer w0.508: P1.4@73.66,90.805 74.93,89.535 D22.1@74.93,86.867 ; v1(74.93,79.883) D23.1@74.93,81.152
  Bottom Layer w0.508: P1.4@73.66,90.805 74.93,89.535 v1(74.93,79.883)
VIN: D1.2 VIN.1 | length 5.6
  Top Layer w2.54: D1.2@72.15,5.715 74.549,5.715 75.184,6.35 VIN.1@77.47,6.35
VPROTECTED: C1.1 D2.3 D3.2 D4.1 K1.1 K1.4 K1.13 K2.4 K2.13 P3.1 P3.2 P4.1 P4.2 Q19.2 R1.1 R96.1 | length 420.3
  Top Layer w0.305: R1.1@37.68,10.795 39.37,10.795 41.91,8.255 41.91,6.985 43.18,5.715 D4.1@45.48,5.715 D4.1@45.72,5.715 ; v1(53.594,31.496) 53.633,31.535 R96.1@54.864,31.535 ; Q19.2@54.93,29.625 R96.1@54.93,31.43
  Top Layer w1.27: P3.2@23.622,78.74 P3.2@23.495,78.74 P3.1@20.955,78.74 20.955,101.981 23.495,104.521 58.928,104.521 62.23,101.219 127.127,101.219 131.318,97.028 131.318,82.931 135.509,78.74 P4.1@137.795,78.74
  Top Layer w2.54: D4.1@45.48,5.715 45.48,9.412 45.72,9.652 C1.1@45.72,14.01 48.601,14.01 52.959,9.652 58.039,9.652 59.69,11.303 K1.1@59.69,12.7 K1.4@67.31,12.7 K1.13@67.31,20.32 K2.4@67.31,24.13 K2.13@67.31,31.75 ; D4.1@45.72,5.715 D3.2@52.705,5.715
  Bottom Layer w0.305: v1(53.594,31.496) 54.864,30.226 62.23,30.226 63.754,31.75 K2.13@67.31,31.75
  Bottom Layer w1.27: K1.4@67.183,12.7 K1.4@67.31,12.7 68.834,12.7 72.136,16.002 91.694,16.002 93.726,13.97 107.188,13.97 108.839,15.621 120.523,15.621 125.476,20.574 125.476,24.257 126.345,25.126 126.345,25.374 127.515,26.543 154.559,26.543 158.369,30.353 158.369,74.295 153.924,78.74 P4.2@140.335,78.74 P4.1@137.795,78.74
VSLAVES: J5.1 J7.1 K1.8 K1.9 | length 50.6
  Top Layer w2.54: K1.9@77.47,20.32 K1.8@77.47,12.7 77.47,11.049 78.994,9.525 87.503,9.525 94.361,2.667 110.102,2.667 J7.1@113.785,6.35
VSWITCHED: D5.2 D8.2 K2.8 K2.9 P3.3 P3.4 P4.3 P4.4 P5.7 P5.8 P5.13 P5.14 Q13.3 Q13X.1 Q14.3 R16.1 R20.1 R90.1 | length 433.5
  Top Layer w0.203: K2.9@77.431,31.838 R20.1@77.431,34.29
  Top Layer w0.508: R16.1@48.387,38.696 v1(48.387,40.005)
  Top Layer w0.762: Q14.3@10.16,69.215 10.16,66.548 11.303,65.405 Q13X.1@14.224,65.405 14.224,66.929 14.605,67.31 R90.1@14.605,68.365 ; Q13.3@15.655,59.055 v1(17.018,59.055)
  Top Layer w1.27: P3.3@20.955,76.2 P3.4@23.495,76.2 25.019,76.2 26.035,77.216 26.035,81.026 22.733,84.328 22.733,100.584 24.892,102.743 58.293,102.743 61.722,99.314 108.585,99.314 ; P5.7@108.585,93.345 P5.8@108.585,95.885 108.585,99.314 ; P5.13@116.205,93.345 P5.14@116.205,95.885 116.205,99.314 ; 116.205,99.441 116.205,99.314 ; P4.4@140.335,76.2 P4.3@137.795,76.2 134.747,76.2 129.413,81.534 129.413,96.52 126.619,99.314 116.205,99.314 ; 108.585,99.314 116.205,99.314
  Top Layer w2.54: v1(130.81,34.417) v1(130.81,35.306) v1(130.81,36.195) D5.2@130.81,38.241 ; v1(130.81,47.752) v1(130.81,48.641) v1(130.81,49.53) D8.2@130.81,51.957
  Bottom Layer w0.508: v1(48.387,40.005) 51.435,40.005 52.451,41.021 59.563,41.021 61.341,39.243 64.389,39.243 69.469,34.163 75.057,34.163 K2.9@77.47,31.75
  Bottom Layer w0.762: v1(17.018,59.055) 17.018,64.77 16.383,65.405 Q13X.1@14.224,65.405 14.224,71.755 18.669,76.2 P3.3@20.955,76.2
  Bottom Layer w1.27: 128.885,32.111 130.81,30.186 130.81,29.083 131.846,28.047 153.142,28.047 156.464,31.369 156.464,73.66 153.924,76.2 P4.4@140.335,76.2 P4.3@137.795,76.2
  Bottom Layer w2.54: K2.8@77.47,24.13 K2.9@77.47,31.75 81.913,31.75 84.345,34.183 91.423,34.183 93.494,32.111 128.885,32.111 130.81,34.036 v1(130.81,34.417) v1(130.81,35.306) v1(130.81,36.195) v1(130.81,47.752) v1(130.81,48.641) v1(130.81,49.53)
pads on no net: D2.2 D19.2 GPS1.1 GPS1.2 GPS1.3 GPS1.4 GPS1.5 GPS1.6 GPS1.7 GPS1.8 GPS1.14 GPS1.15 GPS1.16 GPS1.17 GPS1.18 GPS1.19 ICD.6 K1.6 K1.11 K2.6 K2.11 LCD1.20 LCD1.M1 LCD1.M2 P4.34 SD1.9 SD1.14 SD1.15 U1.2 U1.6 U2.2 U2.6 U15.3 U15.5 U15.6 U15.7 U15.8 U15.9 U15.10 U15.11 U15.12 U15.13 U15.18 U15.21 U15.22 U15.23 U15.25 U15.27 U15.28 U15.29 U15.31 U15.32 U16.11 U16.12 U16.13 U16.14 U16.15 U16.19 U16.20 U16.21 U16.22 U16.23 U16.25 U16.26 U16.45 X2.2 X2.3
copper on no net: | length 142
  Top Layer w0.2: 11.389,1.391 11.389,3.641 13.639,3.641 13.639,1.391 11.389,1.391
  Top Layer w0.254: 10.889,0.891 10.889,4.141 20.889,4.141 20.889,0.891 10.889,0.891
  MidLayer1 w0.2: 13.639,1.391 13.639,3.641 15.889,3.641 15.889,1.391 13.639,1.391
  MidLayer1 w0.254: 10.889,0.891 20.889,0.891 20.889,4.141 10.889,4.141 10.889,0.891
  MidLayer2 w0.2: 15.889,1.391 15.889,3.641 18.139,3.641 18.139,1.391 15.889,1.391
  MidLayer2 w0.254: 10.889,0.891 10.889,4.141 20.889,4.141 20.889,0.891 10.889,0.891
  Bottom Layer w0.2: 18.139,1.391 20.389,1.391 20.389,3.641 18.139,3.641 18.139,1.391
  Bottom Layer w0.254: 10.889,0.891 20.889,0.891 20.889,4.141 10.889,4.141 10.889,0.891

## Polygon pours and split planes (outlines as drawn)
GND on Top Layer "Top - GND" (solid, remove dead copper, pour order 2): 142.875,14.605 151.13,14.605 151.13,0.508 142.875,0.508
3V3USB on MidLayer2 "Mid 2 -3V3USB" (solid, remove dead copper, pour order 4): 0.635,33.655 18.415,33.655 18.415,27.94 31.115,27.94 31.75,27.94 31.75,0.635 0.635,0.635
+5V on MidLayer2 "Mid 2 - 5V" (solid, remove dead copper, pour order 6): 24.765,73.025 24.765,86.995 26.67,86.995 26.67,89.535 128.27,89.535 128.27,100.33 143.51,100.33 143.51,75.565 134.62,75.565 134.62,73.025 142.875,73.025 142.875,37.465 79.375,37.465 79.375,6.35 126.365,6.35 126.365,26.67 159.385,26.67 159.385,107.95 0.635,107.95 0.635,34.29 19.05,34.29 19.05,28.575 48.26,28.575 48.26,38.1 19.05,38.1 19.05,73.025
3V3 on MidLayer2 "Mid 2 - 3V3" (solid, remove dead copper, pour order 8): 133.985,72.39 142.24,72.39 142.24,38.1 78.74,38.1 78.74,5.715 127,5.715 127,26.035 159.385,26.035 159.385,0.635 73.025,0.635 73.025,41.275 78.105,41.275 78.105,49.53 134.62,49.53 134.62,70.485 132.08,70.485 132.08,81.28 140.335,81.28 140.335,97.155 130.81,97.155 130.81,85.09 59.69,85.09 59.69,83.82 28.575,83.82 28.575,69.215 19.685,69.215 19.685,72.39 25.4,72.39 25.4,86.36 27.305,86.36 27.305,88.9 128.905,88.9 128.905,99.695 142.875,99.695 142.875,76.2 133.985,76.2
3V3UC on MidLayer2 "Mid 2 - 3V3" (solid, remove dead copper, pour order 10): 131.445,96.52 139.7,96.52 139.7,81.915 131.445,81.915 131.445,69.85 133.985,69.85 133.985,50.165 77.47,50.165 77.47,41.91 72.39,41.91 72.39,0.635 32.385,0.635 32.385,27.94 48.895,27.94 48.895,38.735 19.685,38.735 19.685,68.58 29.21,68.58 29.21,83.185 60.325,83.185 60.325,84.455 131.445,84.455
GND on MidLayer1 "Mid 1 - GND" (solid, remove dead copper, pour order 12): 0.635,0.635 159.385,0.635 159.385,107.95 0.635,107.95

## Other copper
Top Layer:
  text "T" at 12.019,1.871 h2
MidLayer1:
  text "1" at 14.389,1.891 h2
MidLayer2:
  text "2" at 16.519,1.871 h2
Bottom Layer:
  text "B" at 18.769,1.871 h2

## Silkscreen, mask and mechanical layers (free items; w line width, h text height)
Bottom Overlay:
  circle w0.2: c75.083,72.154 r1.75
  region: 60.085,54.134 60.378,53.427 61.085,53.134 74.335,53.134 75.042,53.427 75.335,54.134 75.335,56.384 75.042,57.091 74.335,57.384 61.085,57.384 60.378,57.091 60.085,56.384
  lines w0.3: 63.676,64.478 63.676,60.033 67.486,60.033 ; 63.676,64.483 67.486,64.483 71.296,64.483 75.106,64.483 ; 67.486,64.478 67.486,60.033 ; 71.296,64.478 71.296,60.033 ; 75.106,64.478 75.106,60.033 71.296,60.033 ; 67.486,60.033 71.296,60.033
  text "C    2014" at 75.677,71.395 h2
  text "AGRIGEL" at 94.107,70.612 h3.5
  text ".PCB_TITLE" at 93.95,67.486 h2.54
  text ".Version" at 88.265,64.262 h2.54
  text "VER" at 93.95,64.236 h2.54
  text "MOD:" at 81.407,61.595 h2.25
  text "C" at 66.726,61.024 h3.5
  text "B" at 70.326,61.024 h3.5
  text "A" at 74.326,61.024 h3.5
  text "ISSUE:" at 82.55,54.229 h2.25
Top Solder:
  rectangle: 10.889,0.891 20.889,4.141
Bottom Solder:
  rectangle: 10.889,0.891 20.889,4.141
Board:
  the board outline again, w0.051
Mechanical 15:
  circle w0.025: c4,105 r2
  circle w0.025: c156,105 r2
  circle w0.025: c156,4 r2
  circle w0.025: c4,4 r2
  lines w0.051: 0,0 160,109 ; 0,4 8,4 ; 0,50.1 6.9,50.1 ; 0,54.5 160,54.5 ; 0,105 8,105 ; 0,109 160,0 ; 4,0 4,8 ; 4,101 4,109 ; 39,95.5 39,109 ; 73.9,80.6 74,109 ; 80,0 80,109 ; 151.5,50.1 160,50.1 ; 152,4 160,4 ; 152,105 160,105 ; 156,0 156,8 ; 156,101 156,109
